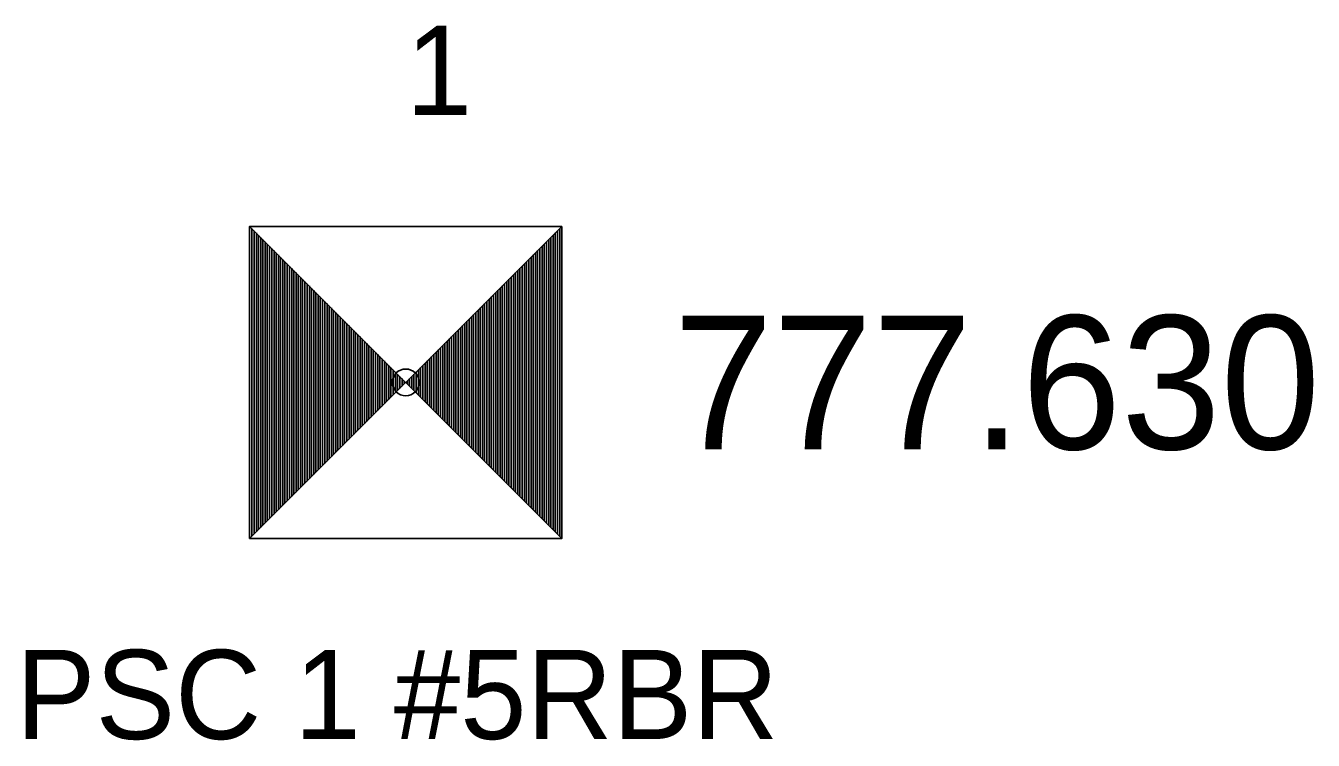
# Model space of a CAD drawing. Extents: x 1736563 to 1738032, y 1150548 to 1154248.
# Drawn here: x 1736645.23 to 1736659.67, y 1150547.62 to 1150555.63 of the extents above; entities that cross this region are included whole.
import ezdxf

# ---------------------------------------------------------------- set-up
doc = ezdxf.new("R2010")
doc.units = 0
for name, color, linetype in [('RD_HC_Survey', 7, 'Continuous'), ('RD_HC_Survey_ELEV', 7, 'Continuous'), ('RD_HC_txCode', 7, 'Continuous'), ('RD_SMD_Locator', 7, 'Continuous')]:
    doc.layers.add(name, color=color, linetype=linetype)

msp = doc.modelspace()

# ---------------------------------------------------------------- linework, layer by layer
at = {"layer": 'RD_HC_Survey'}
for p, q in [((1736647.744, 1150553.38), (1736651.244, 1150549.88)), ((1736651.244, 1150553.38), (1736647.744, 1150549.88)), ((1736647.769, 1150553.356), (1736647.769, 1150549.905)), ((1736651.22, 1150553.356), (1736651.22, 1150549.905)), ((1736647.794, 1150553.331), (1736647.794, 1150549.93)), ((1736647.819, 1150553.306), (1736647.819, 1150549.955)), ((1736647.843, 1150553.281), (1736647.843, 1150549.979)), ((1736647.868, 1150553.257), (1736647.868, 1150550.004)), ((1736647.893, 1150553.232), (1736647.893, 1150550.029)), ((1736651.096, 1150553.232), (1736651.096, 1150550.029)), ((1736651.121, 1150553.257), (1736651.121, 1150550.004)), ((1736651.145, 1150553.281), (1736651.145, 1150549.979)), ((1736651.17, 1150553.306), (1736651.17, 1150549.955)), ((1736651.195, 1150553.331), (1736651.195, 1150549.93)), ((1736647.918, 1150553.207), (1736647.918, 1150550.054)), ((1736647.942, 1150553.182), (1736647.942, 1150550.078)), ((1736647.967, 1150553.158), (1736647.967, 1150550.103)), ((1736647.992, 1150553.133), (1736647.992, 1150550.128)), ((1736648.017, 1150553.108), (1736648.017, 1150550.153)), ((1736648.041, 1150553.083), (1736648.041, 1150550.177)), ((1736650.947, 1150553.083), (1736650.947, 1150550.177)), ((1736650.972, 1150553.108), (1736650.972, 1150550.153)), ((1736650.997, 1150553.133), (1736650.997, 1150550.128)), ((1736651.022, 1150553.158), (1736651.022, 1150550.103)), ((1736651.046, 1150553.182), (1736651.046, 1150550.078)), ((1736651.071, 1150553.207), (1736651.071, 1150550.054)), ((1736648.066, 1150553.059), (1736648.066, 1150550.202)), ((1736648.091, 1150553.034), (1736648.091, 1150550.227)), ((1736648.116, 1150553.009), (1736648.116, 1150550.252)), ((1736648.14, 1150552.984), (1736648.14, 1150550.276)), ((1736648.165, 1150552.96), (1736648.165, 1150550.301)), ((1736648.19, 1150552.935), (1736648.19, 1150550.326)), ((1736650.799, 1150552.935), (1736650.799, 1150550.326)), ((1736650.824, 1150552.96), (1736650.824, 1150550.301)), ((1736650.848, 1150552.984), (1736650.848, 1150550.276)), ((1736650.873, 1150553.009), (1736650.873, 1150550.252)), ((1736650.898, 1150553.034), (1736650.898, 1150550.227)), ((1736650.923, 1150553.059), (1736650.923, 1150550.202)), ((1736648.215, 1150552.91), (1736648.215, 1150550.351)), ((1736648.239, 1150552.885), (1736648.239, 1150550.375)), ((1736648.264, 1150552.861), (1736648.264, 1150550.4)), ((1736648.289, 1150552.836), (1736648.289, 1150550.425)), ((1736648.314, 1150552.811), (1736648.314, 1150550.45)), ((1736648.338, 1150552.786), (1736648.338, 1150550.474)), ((1736650.65, 1150552.786), (1736650.65, 1150550.474)), ((1736650.675, 1150552.811), (1736650.675, 1150550.45)), ((1736650.7, 1150552.836), (1736650.7, 1150550.425)), ((1736650.725, 1150552.861), (1736650.725, 1150550.4)), ((1736650.749, 1150552.885), (1736650.749, 1150550.375)), ((1736650.774, 1150552.91), (1736650.774, 1150550.351)), ((1736648.363, 1150552.762), (1736648.363, 1150550.499)), ((1736648.388, 1150552.737), (1736648.388, 1150550.524)), ((1736648.413, 1150552.712), (1736648.413, 1150550.549)), ((1736648.437, 1150552.687), (1736648.437, 1150550.573)), ((1736648.462, 1150552.663), (1736648.462, 1150550.598)), ((1736648.487, 1150552.638), (1736648.487, 1150550.623)), ((1736650.502, 1150552.638), (1736650.502, 1150550.623)), ((1736650.527, 1150552.663), (1736650.527, 1150550.598)), ((1736650.551, 1150552.687), (1736650.551, 1150550.573)), ((1736650.576, 1150552.712), (1736650.576, 1150550.549)), ((1736650.601, 1150552.737), (1736650.601, 1150550.524)), ((1736650.626, 1150552.762), (1736650.626, 1150550.499)), ((1736648.512, 1150552.613), (1736648.512, 1150550.648)), ((1736648.536, 1150552.588), (1736648.536, 1150550.672)), ((1736648.561, 1150552.564), (1736648.561, 1150550.697)), ((1736648.586, 1150552.539), (1736648.586, 1150550.722)), ((1736648.611, 1150552.514), (1736648.611, 1150550.747)), ((1736648.635, 1150552.489), (1736648.635, 1150550.771)), ((1736650.353, 1150552.489), (1736650.353, 1150550.771)), ((1736650.378, 1150552.514), (1736650.378, 1150550.747)), ((1736650.403, 1150552.539), (1736650.403, 1150550.722)), ((1736650.428, 1150552.564), (1736650.428, 1150550.697)), ((1736650.452, 1150552.588), (1736650.452, 1150550.672)), ((1736650.477, 1150552.613), (1736650.477, 1150550.648)), ((1736648.66, 1150552.465), (1736648.66, 1150550.796)), ((1736648.685, 1150552.44), (1736648.685, 1150550.821)), ((1736648.71, 1150552.415), (1736648.71, 1150550.846)), ((1736648.734, 1150552.39), (1736648.734, 1150550.87)), ((1736648.759, 1150552.366), (1736648.759, 1150550.895)), ((1736650.23, 1150552.366), (1736650.23, 1150550.895)), ((1736650.254, 1150552.39), (1736650.254, 1150550.87)), ((1736650.279, 1150552.415), (1736650.279, 1150550.846)), ((1736650.304, 1150552.44), (1736650.304, 1150550.821)), ((1736650.329, 1150552.465), (1736650.329, 1150550.796)), ((1736648.784, 1150552.341), (1736648.784, 1150550.92)), ((1736648.809, 1150552.316), (1736648.809, 1150550.944)), ((1736648.833, 1150552.291), (1736648.833, 1150550.969)), ((1736648.858, 1150552.267), (1736648.858, 1150550.994)), ((1736648.883, 1150552.242), (1736648.883, 1150551.019)), ((1736648.908, 1150552.217), (1736648.908, 1150551.043)), ((1736650.081, 1150552.217), (1736650.081, 1150551.043)), ((1736650.106, 1150552.242), (1736650.106, 1150551.019)), ((1736650.131, 1150552.267), (1736650.131, 1150550.994)), ((1736650.155, 1150552.291), (1736650.155, 1150550.969)), ((1736650.18, 1150552.316), (1736650.18, 1150550.944)), ((1736650.205, 1150552.341), (1736650.205, 1150550.92)), ((1736648.932, 1150552.192), (1736648.932, 1150551.068)), ((1736648.957, 1150552.168), (1736648.957, 1150551.093)), ((1736648.982, 1150552.143), (1736648.982, 1150551.118)), ((1736649.007, 1150552.118), (1736649.007, 1150551.142)), ((1736649.031, 1150552.093), (1736649.031, 1150551.167)), ((1736649.056, 1150552.069), (1736649.056, 1150551.192)), ((1736649.933, 1150552.069), (1736649.933, 1150551.192)), ((1736649.957, 1150552.093), (1736649.957, 1150551.167)), ((1736649.982, 1150552.118), (1736649.982, 1150551.142)), ((1736650.007, 1150552.143), (1736650.007, 1150551.118)), ((1736650.032, 1150552.168), (1736650.032, 1150551.093)), ((1736650.056, 1150552.192), (1736650.056, 1150551.068)), ((1736649.081, 1150552.044), (1736649.081, 1150551.217)), ((1736649.106, 1150552.019), (1736649.106, 1150551.241)), ((1736649.13, 1150551.994), (1736649.13, 1150551.266)), ((1736649.155, 1150551.97), (1736649.155, 1150551.291)), ((1736649.18, 1150551.945), (1736649.18, 1150551.316)), ((1736649.205, 1150551.92), (1736649.205, 1150551.34)), ((1736649.784, 1150551.92), (1736649.784, 1150551.34)), ((1736649.809, 1150551.945), (1736649.809, 1150551.316)), ((1736649.834, 1150551.97), (1736649.834, 1150551.291)), ((1736649.858, 1150551.994), (1736649.858, 1150551.266)), ((1736649.883, 1150552.019), (1736649.883, 1150551.241)), ((1736649.908, 1150552.044), (1736649.908, 1150551.217)), ((1736649.229, 1150551.895), (1736649.229, 1150551.365)), ((1736649.254, 1150551.871), (1736649.254, 1150551.39)), ((1736649.279, 1150551.846), (1736649.279, 1150551.415)), ((1736649.304, 1150551.821), (1736649.304, 1150551.439)), ((1736649.328, 1150551.796), (1736649.328, 1150551.464)), ((1736649.353, 1150551.772), (1736649.353, 1150551.489)), ((1736649.636, 1150551.772), (1736649.636, 1150551.489)), ((1736649.66, 1150551.796), (1736649.66, 1150551.464)), ((1736649.685, 1150551.821), (1736649.685, 1150551.439)), ((1736649.71, 1150551.846), (1736649.71, 1150551.415)), ((1736649.735, 1150551.871), (1736649.735, 1150551.39)), ((1736649.759, 1150551.895), (1736649.759, 1150551.365)), ((1736649.378, 1150551.747), (1736649.378, 1150551.514)), ((1736649.403, 1150551.722), (1736649.403, 1150551.538)), ((1736649.427, 1150551.697), (1736649.427, 1150551.563)), ((1736649.452, 1150551.673), (1736649.452, 1150551.588)), ((1736649.477, 1150551.648), (1736649.477, 1150551.613)), ((1736649.512, 1150551.648), (1736649.512, 1150551.613)), ((1736649.537, 1150551.673), (1736649.537, 1150551.588)), ((1736649.561, 1150551.697), (1736649.561, 1150551.563)), ((1736649.586, 1150551.722), (1736649.586, 1150551.538)), ((1736649.611, 1150551.747), (1736649.611, 1150551.514))]:
    msp.add_line(p, q, dxfattribs=at)
msp.add_lwpolyline([(1736651.244, 1150553.38), (1736647.744, 1150553.38), (1736647.744, 1150549.88), (1736651.244, 1150549.88)], close=True, dxfattribs=at)
at = {"layer": 'RD_SMD_Locator'}
msp.add_circle((1736649.494, 1150551.63), 0.15, dxfattribs=at)

# ---------------------------------------------------------------- texts
at = {"layer": 'RD_HC_Survey_ELEV'}
msp.add_text('777.630', height=1.5, dxfattribs=at).set_placement((1736652.494, 1150550.88))
at = {"layer": 'RD_HC_txCode'}
for s, p in [('1', (1736649.494, 1150554.63)), ('PSC 1 #5RBR', (1736645.124, 1150547.63))]:
    msp.add_text(s, height=1, dxfattribs=at).set_placement(p)

doc.saveas('drawing.dxf')
